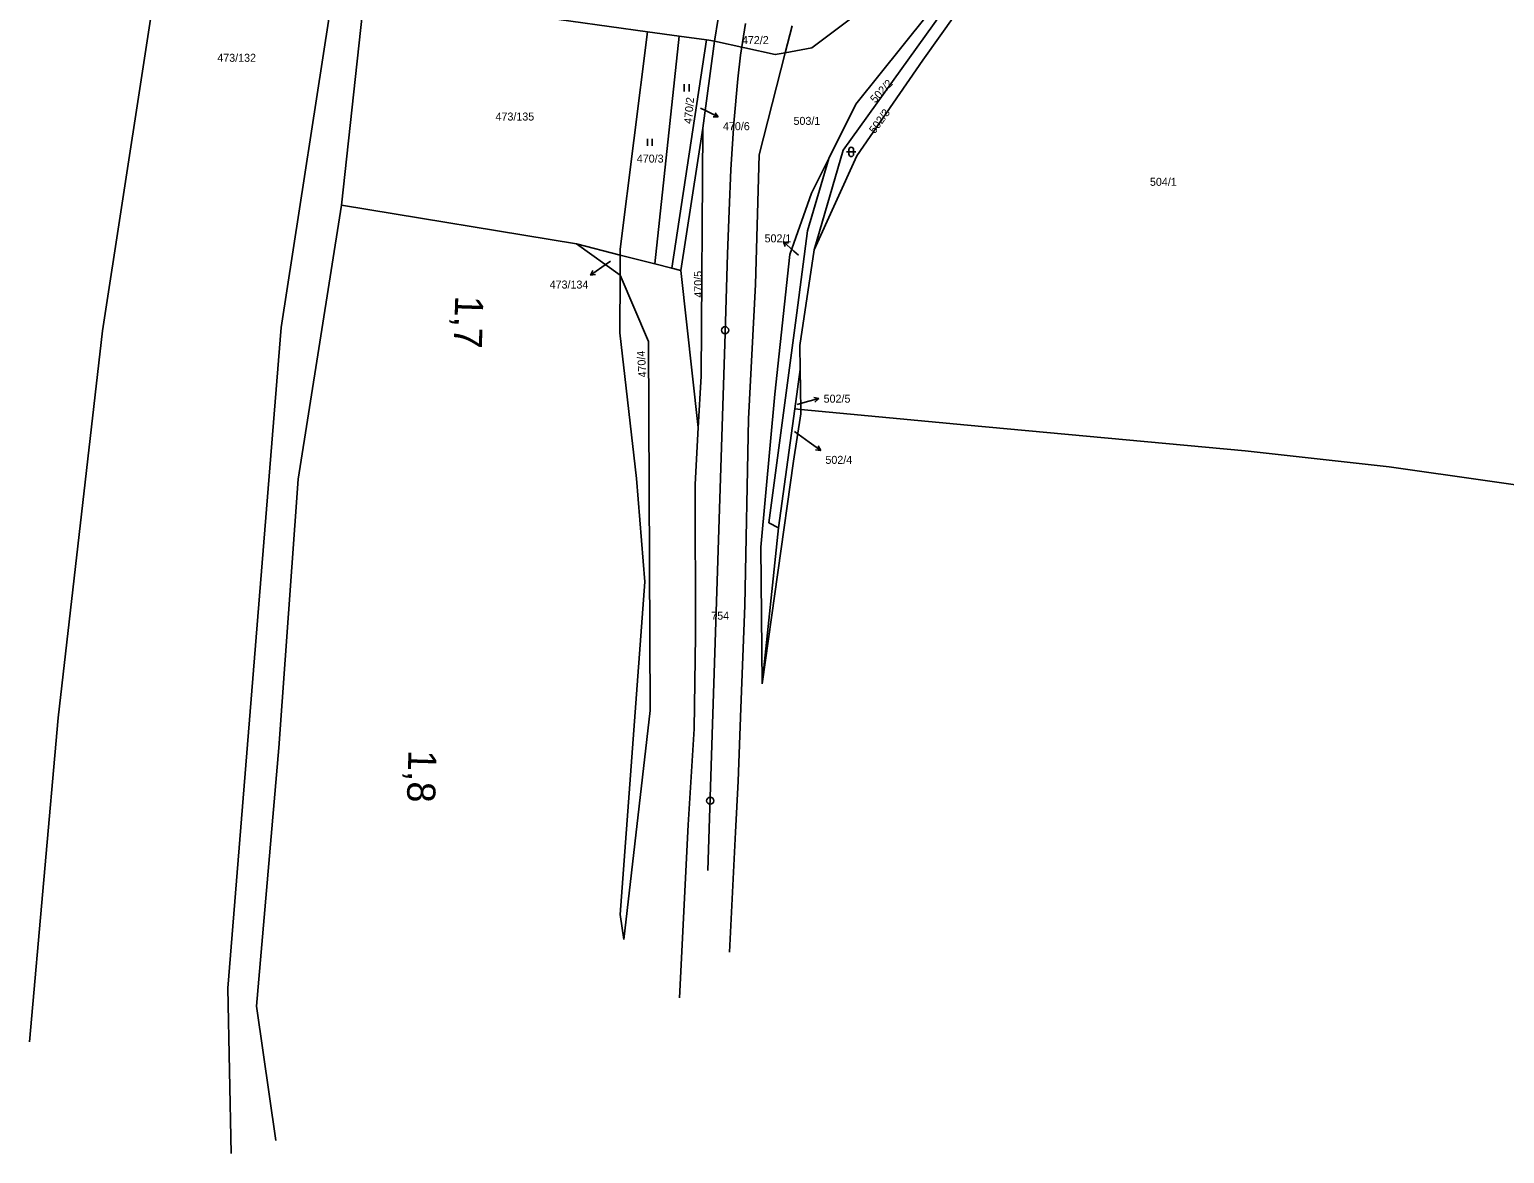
# Model space of a CAD drawing. Extents: x -738085 to -734306, y -1122197 to -1119753.
# Drawn here: x -735623.1 to -735309.7, y -1120761.5 to -1120522.6 of the extents above; entities that cross this region are included whole.
import ezdxf

# ---------------------------------------------------------------- set-up
doc = ezdxf.new("R2010")
doc.units = 0
for name, color, linetype in [('Hranice parcel', 7, 'Continuous'), ('Parcelní čísla', 7, 'Continuous'), ('Pop  PČ popisy', 7, 'Continuous'), ('Vrstva 1', 7, 'Continuous'), ('Vrstva 53', 7, 'Continuous'), ('Vrstva 7', 7, 'Continuous'), ('Značky kultur', 7, 'Continuous')]:
    doc.layers.add(name, color=color, linetype=linetype)

msp = doc.modelspace()

# ---------------------------------------------------------------- linework, layer by layer
at = {"layer": 'Hranice parcel'}
for p, q in [((-735551.72, -1120512.75), (-735556.85, -1120559.89)), ((-735476.81, -1120520.24), (-735477.58, -1120525)), ((-735462.56, -1120527.51), (-735461.09, -1120521.79)), ((-735485.1, -1120523.96), (-735491.79, -1120523.07)), ((-735485.1, -1120523.96), (-735490.27, -1120572.38)), ((-735486.66, -1120573.3), (-735479.26, -1120524.74)), ((-735479.26, -1120524.74), (-735485.1, -1120523.96)), ((-735477.58, -1120525), (-735480.04, -1120543.55)), ((-735480.04, -1120543.55), (-735484.74, -1120573.79)), ((-735480.04, -1120543.55), (-735480.37, -1120596.24)), ((-735506.87, -1120568.14), (-735556.85, -1120559.89)), ((-735497.62, -1120574.79), (-735506.87, -1120568.14)), ((-735497.6, -1120570.51), (-735506.87, -1120568.14)), ((-735497.6, -1120570.51), (-735497.62, -1120574.79)), ((-735490.27, -1120572.38), (-735497.6, -1120570.51)), ((-735486.66, -1120573.3), (-735490.27, -1120572.38)), ((-735484.74, -1120573.79), (-735486.66, -1120573.3)), ((-735481.04, -1120607.15), (-735484.74, -1120573.79)), ((-735480.37, -1120596.24), (-735481.04, -1120607.15)), ((-735460.52, -1120603.19), (-735459.35, -1120594.83)), ((-735459.24, -1120603.31), (-735459.35, -1120594.83)), ((-735463.94, -1120628.53), (-735460.52, -1120603.19)), ((-735459.24, -1120603.31), (-735460.52, -1120603.19)), ((-735467.43, -1120661.66), (-735463.94, -1120628.53))]:
    msp.add_line(p, q, dxfattribs=at)
for points in [[(-735623.13, -1120737.75), (-735617.02, -1120668.92), (-735607.62, -1120586.63), (-735594.77, -1120503.3), (-735584.37, -1120445.06)], [(-735456.38, -1120569.41), (-735450.21, -1120548.21), (-735429.27, -1120518.99), (-735419.55, -1120507.23), (-735411.94, -1120498.5), (-735404.54, -1120493.74)], [(-735456.38, -1120569.41), (-735447.34, -1120549.4), (-735433.29, -1120529.07), (-735419.31, -1120509.3), (-735404.54, -1120493.74)], [(-735462.56, -1120527.51), (-735456.92, -1120526.44), (-735433.71, -1120508.99), (-735418.63, -1120497.17), (-735411.78, -1120494.74)], [(-735580.29, -1120761.53), (-735580.97, -1120726.38), (-735569.66, -1120585.92), (-735558.28, -1120512.02)], [(-735549.79, -1120512.96), (-735543.29, -1120514.47), (-735516.24, -1120519.64), (-735491.79, -1120523.07)], [(-735427.41, -1120513.29), (-735447.57, -1120538.45), (-735453.3, -1120549.98)], [(-735491.79, -1120523.07), (-735497.6, -1120569.24), (-735497.6, -1120570.51)], [(-735477.58, -1120525), (-735478.75, -1120524.81), (-735479.26, -1120524.74)], [(-735462.56, -1120527.51), (-735464.65, -1120527.9), (-735477.58, -1120525)], [(-735471.98, -1120666.86), (-735471.15, -1120644.99), (-735470.37, -1120605.36), (-735468.83, -1120576.77), (-735468.11, -1120549.21), (-735462.56, -1120527.51)], [(-735453.3, -1120549.98), (-735456.94, -1120557.32), (-735461.53, -1120570.37), (-735464.72, -1120600.1), (-735467.74, -1120632.59), (-735467.43, -1120661.66)], [(-735463.94, -1120628.53), (-735466.03, -1120627.41), (-735460.06, -1120582.82), (-735457.81, -1120565.35), (-735453.3, -1120549.98)], [(-735556.85, -1120559.89), (-735566.05, -1120618.15), (-735570.15, -1120675.28), (-735574.88, -1120730.21), (-735570.8, -1120758.76)], [(-735459.35, -1120594.83), (-735459.41, -1120589.72), (-735456.38, -1120569.41)], [(-735497.62, -1120574.79), (-735497.66, -1120587.06), (-735494.14, -1120618.01), (-735492.37, -1120639.98), (-735497.63, -1120710.68), (-735496.83, -1120716)], [(-735497.62, -1120574.79), (-735491.58, -1120588.91), (-735491.21, -1120667.31), (-735496.83, -1120716)], [(-735467.43, -1120661.66), (-735460.81, -1120614.31), (-735459.23, -1120604.25), (-735459.24, -1120603.31)], [(-735459.24, -1120603.31), (-735423.84, -1120606.71), (-735364.81, -1120612.13), (-735334.22, -1120615.52), (-735290.94, -1120621.73)], [(-735481.04, -1120607.15), (-735481.71, -1120619.31), (-735481.61, -1120651.49), (-735481.88, -1120671.27)]]:
    msp.add_lwpolyline(points, dxfattribs=at)
at = {"layer": 'Pop  PČ popisy'}
for p, q in [((-735480.55, -1120539.27), (-735479.46, -1120539.81)), ((-735479.46, -1120539.81), (-735476.76, -1120541.13)), ((-735476.76, -1120541.13), (-735477.88, -1120541.14)), ((-735476.76, -1120541.13), (-735477.44, -1120540.24)), ((-735460.71, -1120569.68), (-735462.94, -1120567.67)), ((-735462.94, -1120567.67), (-735461.86, -1120567.97)), ((-735462.94, -1120567.67), (-735462.53, -1120568.71)), ((-735499.7, -1120571.79), (-735501.48, -1120573.06)), ((-735459.74, -1120570.55), (-735460.71, -1120569.68)), ((-735501.48, -1120573.06), (-735503.94, -1120574.78)), ((-735503.94, -1120574.78), (-735503.41, -1120573.8)), ((-735503.94, -1120574.78), (-735502.83, -1120574.62)), ((-735460, -1120602.26), (-735458.28, -1120601.81)), ((-735458.28, -1120601.81), (-735455.38, -1120601.03)), ((-735455.38, -1120601.03), (-735456.48, -1120600.81)), ((-735455.38, -1120601.03), (-735456.22, -1120601.78)), ((-735460.57, -1120608.03), (-735457.43, -1120610.31)), ((-735457.43, -1120610.31), (-735455, -1120612.07)), ((-735455, -1120612.07), (-735456.11, -1120611.89)), ((-735455, -1120612.07), (-735455.52, -1120611.08))]:
    msp.add_line(p, q, dxfattribs=at)
at = {"layer": 'Vrstva 1'}
for points in [[(-735471.02, -1120521.28), (-735472.03, -1120528.02), (-735472.64, -1120533.02), (-735473.48, -1120542.45), (-735474.08, -1120552.34), (-735474.47, -1120561.09), (-735474.78, -1120570.26), (-735475.33, -1120587.19), (-735475.9, -1120604.74)], [(-735475.9, -1120604.74), (-735477.02, -1120639.86), (-735477.98, -1120670.26), (-735478.96, -1120701.34)]]:
    msp.add_lwpolyline(points, dxfattribs=at)
at = {"layer": 'Vrstva 53'}
msp.add_lwpolyline([(-735485.02, -1120728.4), (-735483.19, -1120691.62), (-735481.88, -1120671.27), (-735481.61, -1120651.49), (-735481.71, -1120619.31), (-735481.04, -1120607.15), (-735480.37, -1120596.24), (-735480.04, -1120543.55), (-735484.74, -1120573.79), (-735486.66, -1120573.3), (-735479.26, -1120524.74), (-735478.75, -1120524.81), (-735477.58, -1120525), (-735464.65, -1120527.9), (-735462.56, -1120527.51), (-735468.11, -1120549.21), (-735468.83, -1120576.77), (-735470.37, -1120605.36), (-735471.15, -1120644.99), (-735471.98, -1120666.86), (-735472.57, -1120682.35), (-735473.1, -1120693.18), (-735474.36, -1120718.72)], dxfattribs=at)
at = {"layer": 'Vrstva 7'}
for centre in [(-735475.31, -1120586.48), (-735478.49, -1120686.52)]:
    msp.add_circle(centre, 0.75, dxfattribs=at)
at = {"layer": 'Značky kultur'}
for p, q in [((-735483.99, -1120535.71), (-735483.99, -1120534.21)), ((-735482.99, -1120535.71), (-735482.99, -1120534.21)), ((-735491.82, -1120547.3), (-735491.82, -1120545.8)), ((-735490.82, -1120547.3), (-735490.82, -1120545.8)), ((-735449.52, -1120548.59), (-735447.52, -1120548.59)), ((-735449.02, -1120548.09), (-735449.02, -1120549.09)), ((-735448.02, -1120549.09), (-735448.02, -1120548.09))]:
    msp.add_line(p, q, dxfattribs=at)
for centre, start, end in [((-735448.52, -1120548.09), 0, 180), ((-735448.52, -1120549.09), 180, 359.9879)]:
    msp.add_arc(centre, 0.5, start, end, dxfattribs=at)

# ---------------------------------------------------------------- texts
at = {"layer": 'Parcelní čísla'}
for s, p in [('472/2', (-735471.74, -1120525.65)), ('473/132', (-735583.22, -1120529.42)), ('473/135', (-735524.1, -1120541.91)), ('503/1', (-735460.78, -1120542.83)), ('470/6', (-735475.77, -1120543.96)), ('470/3', (-735494.08, -1120550.85)), ('504/1', (-735385.04, -1120555.79)), ('502/1', (-735466.93, -1120567.81)), ('473/134', (-735512.6, -1120577.63)), ('502/5', (-735454.38, -1120601.89)), ('502/4', (-735454, -1120614.9)), ('754', (-735478.26, -1120648.03))]:
    msp.add_text(s, height=1.7, dxfattribs=at).set_placement(p)
for s, rotation, p in [('502/2', 47, (-735443.44, -1120538.31)), ('470/2', 85, (-735482.39, -1120542.69)), ('502/3', 54, (-735443.51, -1120544.83)), ('470/5', 91, (-735480.15, -1120579.55)), ('470/4', 94, (-735492, -1120596.47))]:
    msp.add_text(s, height=1.7, rotation=rotation, dxfattribs=at).set_placement(p)
at = {"layer": 'Vrstva 7'}
for s, rotation, p in [('1,7', 268.1331, (-735532.65, -1120579.1)), ('1,8', 268.1993, (-735542.59, -1120675.68))]:
    msp.add_text(s, height=6, rotation=rotation, dxfattribs=at).set_placement(p)

doc.saveas('drawing.dxf')
